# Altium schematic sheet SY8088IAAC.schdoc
size 127 x 101 mm
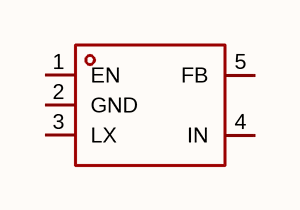
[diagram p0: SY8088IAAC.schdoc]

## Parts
U?  sy8088iaac  [SOT-23-5_L3.0-W1.7-P0.95-LS2.8-BL]  (value not drawn)

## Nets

Not connected (* = marked no-connect by the designer): U? 1(EN) 2(GND) 3(LX) 4(IN) 5(FB)

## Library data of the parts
U? = sy8088iaac: 功能类型:降压型;工作电压:2.5V~5.5V;输出电压:-;输出电流:1A;输出类型:可调;; Manufacturer: Silergy(矽力杰); AddInBom: yes; ModelId: 0a2a1b8f50944f73965918ad6e5fe167; ModelName: SOT-23-5_L2.9-W1.6-H1.1-LS2.8-P0.95; ModelTransform: 118.60433,114.173,0,90,0,0,0.0005,0.0005,0; Function: 降压型; Output Current: 1A; Frequency - Switching: 1.5MHz; Synchronous Rectifier: 是; Number of Outputs: 1; Topology: 降压式; Quiescent Current: 50uA; Switch tube (built-in/external): 内置; Output Type: 可调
